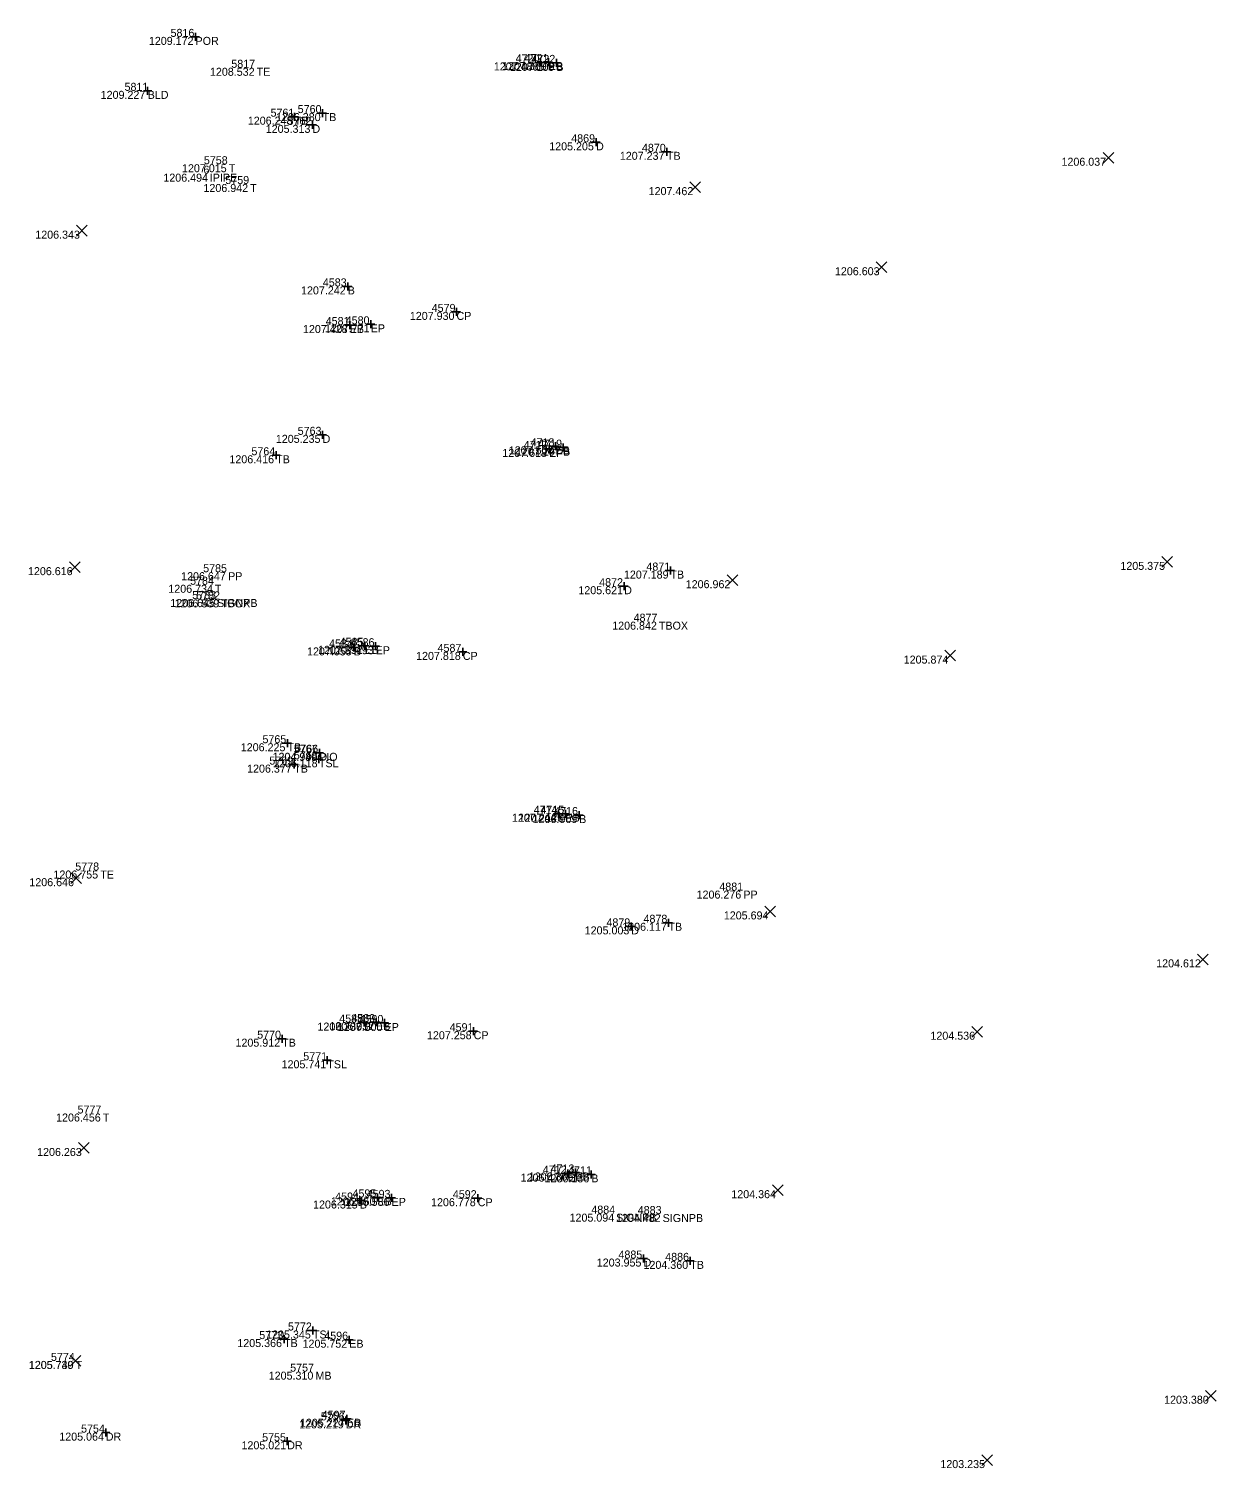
# Model space of a CAD drawing. Extents: x 2044997 to 2050342, y 455233 to 458054.
# Drawn here: x 2047583.8 to 2047732.1, y 456651.5 to 456831.4 of the extents above; entities that cross this region are included whole.
import ezdxf

# ---------------------------------------------------------------- set-up
doc = ezdxf.new("R2010")
doc.units = 0
for name, color, linetype in [('SV_X_Random_Point', 7, 'Continuous'), ('SV_X_Shot_Marker', 7, 'Continuous'), ('SV_X_Text_Comment', 7, 'Continuous'), ('SV_X_Text_Elevation', 7, 'Continuous'), ('SV_X_Text_Name', 7, 'Continuous')]:
    doc.layers.add(name, color=color, linetype=linetype)

msp = doc.modelspace()

# ---------------------------------------------------------------- linework, layer by layer
at = {"layer": 'SV_X_Random_Point'}
for p, q in [((2047718.03, 456814.57), (2047719.36, 456815.9)), ((2047718.03, 456815.9), (2047719.36, 456814.57)), ((2047666.41, 456810.91), (2047667.74, 456812.24)), ((2047666.41, 456812.24), (2047667.74, 456810.91)), ((2047589.79, 456805.46), (2047591.12, 456806.8)), ((2047589.79, 456806.8), (2047591.12, 456805.46)), ((2047689.68, 456800.89), (2047691.01, 456802.23)), ((2047689.68, 456802.23), (2047691.01, 456800.89)), ((2047588.89, 456763.42), (2047590.23, 456764.76)), ((2047588.89, 456764.76), (2047590.23, 456763.42)), ((2047725.36, 456764.08), (2047726.69, 456765.41)), ((2047725.36, 456765.41), (2047726.69, 456764.08)), ((2047671.05, 456761.8), (2047672.38, 456763.13)), ((2047671.05, 456763.13), (2047672.38, 456761.8)), ((2047698.25, 456752.38), (2047699.59, 456753.71)), ((2047698.25, 456753.71), (2047699.59, 456752.38)), ((2047589.06, 456724.56), (2047590.4, 456725.9)), ((2047589.06, 456725.9), (2047590.4, 456724.56)), ((2047675.78, 456720.41), (2047677.11, 456721.74)), ((2047675.78, 456721.74), (2047677.11, 456720.41)), ((2047729.81, 456714.42), (2047731.15, 456715.75)), ((2047729.81, 456715.75), (2047731.15, 456714.42)), ((2047701.62, 456705.38), (2047702.95, 456706.71)), ((2047701.62, 456706.71), (2047702.95, 456705.38)), ((2047590.02, 456690.86), (2047591.35, 456692.19)), ((2047590.02, 456692.19), (2047591.35, 456690.86)), ((2047676.72, 456685.58), (2047678.05, 456686.92)), ((2047676.72, 456686.92), (2047678.05, 456685.58)), ((2047588.97, 456664.25), (2047590.31, 456665.58)), ((2047588.97, 456665.58), (2047590.31, 456664.25)), ((2047730.81, 456659.9), (2047732.15, 456661.23)), ((2047730.81, 456661.23), (2047732.15, 456659.9)), ((2047702.87, 456651.86), (2047704.2, 456653.2)), ((2047702.87, 456653.2), (2047704.2, 456651.86))]:
    msp.add_line(p, q, dxfattribs=at)
at = {"layer": 'SV_X_Shot_Marker'}
for p, q in [((2047604.65, 456830.84), (2047604.65, 456829.84)), ((2047604.15, 456830.34), (2047605.15, 456830.34)), ((2047604.65, 456830.34), (2047604.65, 456830.34)), ((2047647.75, 456827.65), (2047647.75, 456826.65)), ((2047648.26, 456827.2), (2047649.26, 456827.2)), ((2047648.76, 456827.7), (2047648.76, 456826.7)), ((2047648.76, 456827.2), (2047648.76, 456827.2)), ((2047649.72, 456827.59), (2047649.72, 456826.59)), ((2047647.25, 456827.15), (2047648.25, 456827.15)), ((2047647.75, 456827.15), (2047647.75, 456827.15)), ((2047649.22, 456827.09), (2047650.22, 456827.09)), ((2047649.72, 456827.09), (2047649.72, 456827.09)), ((2047598.17, 456823.6), (2047599.17, 456823.6)), ((2047598.67, 456824.1), (2047598.67, 456823.1)), ((2047598.67, 456823.6), (2047598.67, 456823.6)), ((2047616.52, 456820.37), (2047617.52, 456820.37)), ((2047617.02, 456820.87), (2047617.02, 456819.87)), ((2047617.02, 456820.37), (2047617.02, 456820.37)), ((2047620.03, 456820.82), (2047621.03, 456820.82)), ((2047620.53, 456821.32), (2047620.53, 456820.32)), ((2047620.53, 456820.82), (2047620.53, 456820.82)), ((2047618.75, 456819.35), (2047619.75, 456819.35)), ((2047619.25, 456819.85), (2047619.25, 456818.85)), ((2047619.25, 456819.35), (2047619.25, 456819.35)), ((2047654.18, 456817.17), (2047655.18, 456817.17)), ((2047654.68, 456817.67), (2047654.68, 456816.67)), ((2047654.68, 456817.17), (2047654.68, 456817.17)), ((2047663.53, 456816.48), (2047663.53, 456815.48)), ((2047663.03, 456815.98), (2047664.03, 456815.98)), ((2047663.53, 456815.98), (2047663.53, 456815.98)), ((2047623.16, 456799.17), (2047624.16, 456799.17)), ((2047623.66, 456799.67), (2047623.66, 456798.67)), ((2047623.66, 456799.17), (2047623.66, 456799.17)), ((2047623.91, 456794.84), (2047623.91, 456793.84)), ((2047626.53, 456794.93), (2047626.53, 456793.93)), ((2047636.75, 456795.98), (2047637.75, 456795.98)), ((2047637.25, 456796.48), (2047637.25, 456795.48)), ((2047637.25, 456795.98), (2047637.25, 456795.98)), ((2047623.41, 456794.34), (2047624.41, 456794.34)), ((2047623.91, 456794.34), (2047623.91, 456794.34)), ((2047626.03, 456794.43), (2047627.03, 456794.43)), ((2047626.53, 456794.43), (2047626.53, 456794.43)), ((2047620.02, 456780.62), (2047621.02, 456780.62)), ((2047620.52, 456781.12), (2047620.52, 456780.12)), ((2047620.52, 456780.62), (2047620.52, 456780.62)), ((2047648.31, 456778.86), (2047649.31, 456778.86)), ((2047648.81, 456779.36), (2047648.81, 456778.36)), ((2047648.81, 456778.86), (2047648.81, 456778.86)), ((2047649.12, 456779.19), (2047650.12, 456779.19)), ((2047649.62, 456779.69), (2047649.62, 456778.69)), ((2047649.62, 456779.19), (2047649.62, 456779.19)), ((2047650.06, 456779.02), (2047651.06, 456779.02)), ((2047650.56, 456779.52), (2047650.56, 456778.52)), ((2047650.56, 456779.02), (2047650.56, 456779.02)), ((2047614.22, 456778.07), (2047615.22, 456778.07)), ((2047614.72, 456778.57), (2047614.72, 456777.57)), ((2047614.72, 456778.07), (2047614.72, 456778.07)), ((2047663.47, 456763.66), (2047664.47, 456763.66)), ((2047663.97, 456764.16), (2047663.97, 456763.16)), ((2047663.97, 456763.66), (2047663.97, 456763.66)), ((2047657.69, 456761.71), (2047658.69, 456761.71)), ((2047658.19, 456762.21), (2047658.19, 456761.21)), ((2047658.19, 456761.71), (2047658.19, 456761.71)), ((2047623.92, 456754.06), (2047624.92, 456754.06)), ((2047624.42, 456754.56), (2047624.42, 456753.56)), ((2047624.42, 456754.06), (2047624.42, 456754.06)), ((2047625.28, 456754.26), (2047626.28, 456754.26)), ((2047625.78, 456754.76), (2047625.78, 456753.76)), ((2047625.78, 456754.26), (2047625.78, 456754.26)), ((2047626.65, 456754.21), (2047627.65, 456754.21)), ((2047627.15, 456754.71), (2047627.15, 456753.71)), ((2047627.15, 456754.21), (2047627.15, 456754.21)), ((2047637.54, 456753.5), (2047638.54, 456753.5)), ((2047638.04, 456754), (2047638.04, 456753)), ((2047638.04, 456753.5), (2047638.04, 456753.5)), ((2047615.64, 456742.09), (2047616.64, 456742.09)), ((2047616.14, 456742.59), (2047616.14, 456741.59)), ((2047616.14, 456742.09), (2047616.14, 456742.09)), ((2047619.62, 456740.9), (2047620.62, 456740.9)), ((2047620.12, 456741.4), (2047620.12, 456740.4)), ((2047620.12, 456740.9), (2047620.12, 456740.9)), ((2047616.47, 456739.42), (2047617.47, 456739.42)), ((2047616.97, 456739.92), (2047616.97, 456738.92)), ((2047616.97, 456739.42), (2047616.97, 456739.42)), ((2047619.56, 456740.09), (2047620.56, 456740.09)), ((2047620.06, 456740.59), (2047620.06, 456739.59)), ((2047620.06, 456740.09), (2047620.06, 456740.09)), ((2047649.98, 456733.78), (2047649.98, 456732.78)), ((2047650.85, 456733.78), (2047650.85, 456732.78)), ((2047649.48, 456733.28), (2047650.48, 456733.28)), ((2047649.98, 456733.28), (2047649.98, 456733.28)), ((2047650.35, 456733.28), (2047651.35, 456733.28)), ((2047650.85, 456733.28), (2047650.85, 456733.28)), ((2047652.07, 456733.12), (2047653.07, 456733.12)), ((2047652.57, 456733.62), (2047652.57, 456732.62)), ((2047652.57, 456733.12), (2047652.57, 456733.12)), ((2047659.08, 456719.71), (2047659.08, 456718.71)), ((2047663.23, 456719.66), (2047664.23, 456719.66)), ((2047663.73, 456720.16), (2047663.73, 456719.16)), ((2047663.73, 456719.66), (2047663.73, 456719.66)), ((2047658.58, 456719.21), (2047659.58, 456719.21)), ((2047659.08, 456719.21), (2047659.08, 456719.21)), ((2047625.22, 456707.19), (2047626.22, 456707.19)), ((2047625.72, 456707.69), (2047625.72, 456706.69)), ((2047625.72, 456707.19), (2047625.72, 456707.19)), ((2047626.71, 456707.25), (2047627.71, 456707.25)), ((2047627.21, 456707.75), (2047627.21, 456706.75)), ((2047627.21, 456707.25), (2047627.21, 456707.25)), ((2047627.76, 456707.14), (2047628.76, 456707.14)), ((2047628.26, 456707.64), (2047628.26, 456706.64)), ((2047628.26, 456707.14), (2047628.26, 456707.14)), ((2047614.97, 456705.18), (2047615.97, 456705.18)), ((2047615.47, 456705.68), (2047615.47, 456704.68)), ((2047615.47, 456705.18), (2047615.47, 456705.18)), ((2047638.89, 456706.11), (2047639.89, 456706.11)), ((2047639.39, 456706.61), (2047639.39, 456705.61)), ((2047639.39, 456706.11), (2047639.39, 456706.11)), ((2047620.61, 456702.48), (2047621.61, 456702.48)), ((2047621.11, 456702.98), (2047621.11, 456701.98)), ((2047621.11, 456702.48), (2047621.11, 456702.48)), ((2047651.14, 456688.82), (2047651.14, 456687.82)), ((2047652.11, 456688.96), (2047652.11, 456687.96)), ((2047654.09, 456688.73), (2047654.09, 456687.73)), ((2047650.64, 456688.32), (2047651.64, 456688.32)), ((2047651.14, 456688.32), (2047651.14, 456688.32)), ((2047651.61, 456688.46), (2047652.61, 456688.46)), ((2047652.11, 456688.46), (2047652.11, 456688.46)), ((2047653.59, 456688.23), (2047654.59, 456688.23)), ((2047654.09, 456688.23), (2047654.09, 456688.23)), ((2047625.18, 456685.46), (2047625.18, 456684.46)), ((2047626.88, 456685.35), (2047627.88, 456685.35)), ((2047627.38, 456685.85), (2047627.38, 456684.85)), ((2047627.38, 456685.35), (2047627.38, 456685.35)), ((2047628.64, 456685.29), (2047629.64, 456685.29)), ((2047629.14, 456685.79), (2047629.14, 456684.79)), ((2047629.14, 456685.29), (2047629.14, 456685.29)), ((2047639.4, 456685.25), (2047640.4, 456685.25)), ((2047639.9, 456685.75), (2047639.9, 456684.75)), ((2047639.9, 456685.25), (2047639.9, 456685.25)), ((2047624.68, 456684.96), (2047625.68, 456684.96)), ((2047625.18, 456684.96), (2047625.18, 456684.96)), ((2047660.61, 456678.21), (2047660.61, 456677.21)), ((2047660.11, 456677.71), (2047661.11, 456677.71)), ((2047660.61, 456677.71), (2047660.61, 456677.71)), ((2047665.95, 456677.42), (2047666.95, 456677.42)), ((2047666.45, 456677.92), (2047666.45, 456676.92)), ((2047666.45, 456677.42), (2047666.45, 456677.42)), ((2047619.32, 456669.22), (2047619.32, 456668.22)), ((2047615.21, 456667.65), (2047616.21, 456667.65)), ((2047615.71, 456668.15), (2047615.71, 456667.15)), ((2047615.71, 456667.65), (2047615.71, 456667.65)), ((2047618.82, 456668.72), (2047619.82, 456668.72)), ((2047619.32, 456668.72), (2047619.32, 456668.72)), ((2047623.35, 456667.57), (2047624.35, 456667.57)), ((2047623.85, 456668.07), (2047623.85, 456667.07)), ((2047623.85, 456667.57), (2047623.85, 456667.57)), ((2047623.57, 456658.19), (2047623.57, 456657.19)), ((2047593.44, 456656.46), (2047593.44, 456655.46)), ((2047622.91, 456657.49), (2047623.91, 456657.49)), ((2047623.07, 456657.69), (2047624.07, 456657.69)), ((2047623.41, 456657.99), (2047623.41, 456656.99)), ((2047623.41, 456657.49), (2047623.41, 456657.49)), ((2047623.57, 456657.69), (2047623.57, 456657.69)), ((2047592.94, 456655.96), (2047593.94, 456655.96)), ((2047593.44, 456655.96), (2047593.44, 456655.96)), ((2047615.6, 456654.88), (2047616.6, 456654.88)), ((2047616.1, 456655.38), (2047616.1, 456654.38)), ((2047616.1, 456654.88), (2047616.1, 456654.88))]:
    msp.add_line(p, q, dxfattribs=at)

# ---------------------------------------------------------------- texts
at = {"layer": 'SV_X_Text_Comment'}
for s, p in [('POR', (2047604.65, 456829.34)), ('EB', (2047648.76, 456826.2)), ('TE', (2047612.28, 456825.48)), ('EP', (2047647.75, 456826.15)), ('B', (2047649.72, 456826.09)), ('BLD', (2047598.67, 456822.6)), ('TB', (2047617.02, 456819.37)), ('TB', (2047620.53, 456819.82)), ('D', (2047619.25, 456818.35)), ('D', (2047654.68, 456816.17)), ('TB', (2047663.53, 456814.98)), ('IPIPE', (2047606.43, 456812.25)), ('T', (2047608.8, 456813.43)), ('T', (2047611.47, 456810.96)), ('B', (2047623.66, 456798.17)), ('CP', (2047637.25, 456794.98)), ('EB', (2047623.91, 456793.34)), ('EP', (2047626.53, 456793.43)), ('D', (2047620.52, 456779.62)), ('EP', (2047648.81, 456777.86)), ('EB', (2047649.62, 456778.19)), ('B', (2047650.56, 456778.02)), ('TB', (2047614.72, 456777.07)), ('PP', (2047608.72, 456762.46)), ('TB', (2047663.97, 456762.66)), ('T', (2047607.06, 456760.89)), ('D', (2047658.19, 456760.71)), ('SIGNPB', (2047607.34, 456759.11)), ('TBOX', (2047607.84, 456759.06)), ('TBOX', (2047662.53, 456756.28)), ('B', (2047624.42, 456753.06)), ('EB', (2047625.78, 456753.26)), ('EP', (2047627.15, 456753.21)), ('CP', (2047638.04, 456752.5)), ('TB', (2047616.14, 456741.09)), ('PIO', (2047620.09, 456739.89)), ('D', (2047620.12, 456739.9)), ('TB', (2047616.97, 456738.42)), ('TSL', (2047620.06, 456739.09)), ('EP', (2047649.98, 456732.28)), ('EB', (2047650.85, 456732.28)), ('B', (2047652.57, 456732.12)), ('TE', (2047592.75, 456725.19)), ('PP', (2047673.08, 456722.68)), ('TB', (2047663.73, 456718.66)), ('D', (2047659.08, 456718.21)), ('B', (2047625.72, 456706.19)), ('EB', (2047627.21, 456706.25)), ('EP', (2047628.26, 456706.14)), ('TB', (2047615.47, 456704.18)), ('CP', (2047639.39, 456705.11)), ('TSL', (2047621.11, 456701.48)), ('T', (2047593.07, 456694.83)), ('EP', (2047651.14, 456687.32)), ('EB', (2047652.11, 456687.46)), ('B', (2047654.09, 456687.23)), ('EB', (2047627.38, 456684.35)), ('EP', (2047629.14, 456684.29)), ('CP', (2047639.9, 456684.25)), ('B', (2047625.18, 456683.96)), ('SIGNPB', (2047657.18, 456682.32)), ('SIGNPB', (2047663, 456682.27)), ('D', (2047660.61, 456676.71)), ('TB', (2047666.45, 456676.42)), ('TB', (2047615.71, 456666.65)), ('TSL', (2047619.32, 456667.72)), ('EB', (2047623.85, 456666.57)), ('T', (2047589.68, 456663.92)), ('MB', (2047619.63, 456662.58)), ('DR', (2047623.41, 456656.49)), ('EB', (2047623.57, 456656.69)), ('DR', (2047593.44, 456654.96)), ('DR', (2047616.1, 456653.88))]:
    msp.add_text(s, height=1, dxfattribs=at).set_placement(p)
at = {"layer": 'SV_X_Text_Elevation'}
for s, p in [('1209.172', (2047598.82, 456829.34)), ('1207.389', (2047642.94, 456826.2)), ('1208.532', (2047606.45, 456825.48)), ('1207.488', (2047641.91, 456826.15)), ('1207.109', (2047643.91, 456826.09)), ('1209.227', (2047592.8, 456822.6)), ('1206.248', (2047611.18, 456819.37)), ('1206.380', (2047614.7, 456819.82)), ('1205.313', (2047613.42, 456818.35)), ('1205.205', (2047648.83, 456816.17)), ('1207.237', (2047657.65, 456814.98)), ('1206.037', (2047712.82, 456814.24)), ('1206.494', (2047600.63, 456812.25)), ('1207.015', (2047602.96, 456813.43)), ('1206.942', (2047605.64, 456810.96)), ('1207.462', (2047661.25, 456810.57)), ('1206.343', (2047584.63, 456805.13)), ('1206.603', (2047684.52, 456800.56)), ('1207.242', (2047617.83, 456798.17)), ('1207.930', (2047631.42, 456794.98)), ('1207.428', (2047618.07, 456793.34)), ('1207.771', (2047620.81, 456793.43)), ('1205.235', (2047614.68, 456779.62)), ('1207.618', (2047642.97, 456777.86)), ('1207.508', (2047643.78, 456778.19)), ('1207.297', (2047644.68, 456778.02)), ('1206.416', (2047608.88, 456777.07)), ('1205.375', (2047720.18, 456763.75)), ('1206.616', (2047583.72, 456763.09)), ('1206.647', (2047602.85, 456762.46)), ('1207.189', (2047658.16, 456762.66)), ('1206.962', (2047665.88, 456761.46)), ('1206.734', (2047601.25, 456760.89)), ('1205.621', (2047652.47, 456760.71)), ('1206.645', (2047601.49, 456759.11)), ('1206.539', (2047602.03, 456759.06)), ('1206.842', (2047656.7, 456756.28)), ('1207.055', (2047618.58, 456753.06)), ('1207.392', (2047619.95, 456753.26)), ('1207.493', (2047621.33, 456753.21)), ('1207.818', (2047632.2, 456752.5)), ('1205.874', (2047693.11, 456752.04)), ('1206.225', (2047610.3, 456741.09)), ('1204.939', (2047614.27, 456739.89)), ('1204.940', (2047614.28, 456739.9)), ('1206.377', (2047611.09, 456738.42)), ('1206.118', (2047614.32, 456739.09)), ('1207.244', (2047644.17, 456732.28)), ('1207.128', (2047645.01, 456732.28)), ('1206.909', (2047646.76, 456732.12)), ('1206.646', (2047583.89, 456724.23)), ('1206.755', (2047586.9, 456725.19)), ('1206.276', (2047667.24, 456722.68)), ('1205.694', (2047670.64, 456720.08)), ('1206.117', (2047657.95, 456718.66)), ('1205.003', (2047653.26, 456718.21)), ('1204.612', (2047724.65, 456714.09)), ('1206.730', (2047619.88, 456706.19)), ('1206.932', (2047621.38, 456706.25)), ('1207.000', (2047622.42, 456706.14)), ('1205.912', (2047609.64, 456704.18)), ('1207.258', (2047633.56, 456705.11)), ('1204.536', (2047696.45, 456705.05)), ('1205.741', (2047615.4, 456701.48)), ('1206.456', (2047587.23, 456694.83)), ('1206.263', (2047584.86, 456690.52)), ('1206.477', (2047645.26, 456687.32)), ('1206.366', (2047646.27, 456687.46)), ('1206.136', (2047648.25, 456687.23)), ('1206.450', (2047621.55, 456684.35)), ('1206.586', (2047623.3, 456684.29)), ('1206.778', (2047634.07, 456684.25)), ('1204.364', (2047671.58, 456685.25)), ('1206.315', (2047619.33, 456683.96)), ('1205.094', (2047651.37, 456682.32)), ('1204.482', (2047657.17, 456682.27)), ('1203.955', (2047654.77, 456676.71)), ('1204.360', (2047660.61, 456676.42)), ('1205.366', (2047609.87, 456666.65)), ('1205.345', (2047613.47, 456667.72)), ('1205.752', (2047618.02, 456666.57)), ('1205.739', (2047583.82, 456663.91)), ('1205.740', (2047583.84, 456663.92)), ('1205.310', (2047613.79, 456662.58)), ('1203.380', (2047725.64, 456659.57)), ('1205.219', (2047617.59, 456656.49)), ('1205.227', (2047617.69, 456656.69)), ('1205.064', (2047587.63, 456654.96)), ('1205.021', (2047610.39, 456653.88)), ('1203.235', (2047697.69, 456651.53))]:
    msp.add_text(s, height=1, dxfattribs=at).set_placement(p)
at = {"layer": 'SV_X_Text_Name'}
for s, p in [('5816', (2047601.53, 456830.34)), ('5817', (2047609.12, 456826.48)), ('4720', (2047644.63, 456827.15)), ('4721', (2047645.76, 456827.2)), ('4722', (2047646.61, 456827.09)), ('5811', (2047595.78, 456823.6)), ('5760', (2047617.41, 456820.82)), ('5761', (2047614.02, 456820.37)), ('5762', (2047616.14, 456819.35)), ('4869', (2047651.58, 456817.17)), ('4870', (2047660.41, 456815.98)), ('5758', (2047605.69, 456814.43)), ('6', (2047605.64, 456813.25)), ('5759', (2047608.37, 456811.96)), ('4583', (2047620.55, 456799.17)), ('4579', (2047634.15, 456795.98)), ('4581', (2047620.91, 456794.34)), ('4580', (2047623.41, 456794.43)), ('5763', (2047617.41, 456780.62)), ('5764', (2047611.63, 456778.07)), ('4717', (2047645.64, 456778.86)), ('4718', (2047646.5, 456779.19)), ('4719', (2047647.46, 456779.02)), ('5785', (2047605.6, 456763.46)), ('4871', (2047660.97, 456763.66)), ('5784', (2047603.97, 456761.89)), ('4872', (2047655.07, 456761.71)), ('5783', (2047604.23, 456760.11)), ('5782', (2047604.73, 456760.06)), ('4877', (2047659.37, 456757.28)), ('4585', (2047622.65, 456754.26)), ('4584', (2047621.33, 456754.06)), ('4586', (2047624.03, 456754.21)), ('4587', (2047634.88, 456753.5)), ('5765', (2047613.01, 456742.09)), ('5767', (2047616.92, 456740.89)), ('5768', (2047616.94, 456740.09)), ('5766', (2047616.99, 456740.9)), ('5769', (2047613.87, 456739.42)), ('4714', (2047646.89, 456733.28)), ('4715', (2047647.72, 456733.28)), ('4716', (2047649.45, 456733.12)), ('5778', (2047589.63, 456726.19)), ('4881', (2047670.08, 456723.68)), ('4879', (2047655.98, 456719.21)), ('4878', (2047660.61, 456719.66)), ('4588', (2047622.6, 456707.19)), ('4589', (2047624.11, 456707.25)), ('4590', (2047625.14, 456707.14)), ('4591', (2047636.39, 456706.11)), ('5770', (2047612.35, 456705.18)), ('5771', (2047618.11, 456702.48)), ('5777', (2047589.91, 456695.83)), ('4712', (2047648.02, 456688.32)), ('4713', (2047649, 456688.46)), ('4711', (2047651.19, 456688.23)), ('4594', (2047622.09, 456684.96)), ('4595', (2047624.26, 456685.35)), ('4593', (2047626.03, 456685.29)), ('4592', (2047636.79, 456685.25)), ('4884', (2047654.09, 456683.32)), ('4883', (2047659.89, 456683.27)), ('4885', (2047657.48, 456677.71)), ('4886', (2047663.32, 456677.42)), ('5772', (2047616.2, 456668.72)), ('5773', (2047612.61, 456667.65)), ('4596', (2047620.73, 456667.57)), ('5774', (2047586.59, 456664.92)), ('5757', (2047616.47, 456663.58)), ('5756', (2047620.29, 456657.49)), ('4597', (2047620.41, 456657.69)), ('5754', (2047590.35, 456655.96)), ('5755', (2047612.97, 456654.88))]:
    msp.add_text(s, height=1, dxfattribs=at).set_placement(p)

doc.saveas('drawing.dxf')
